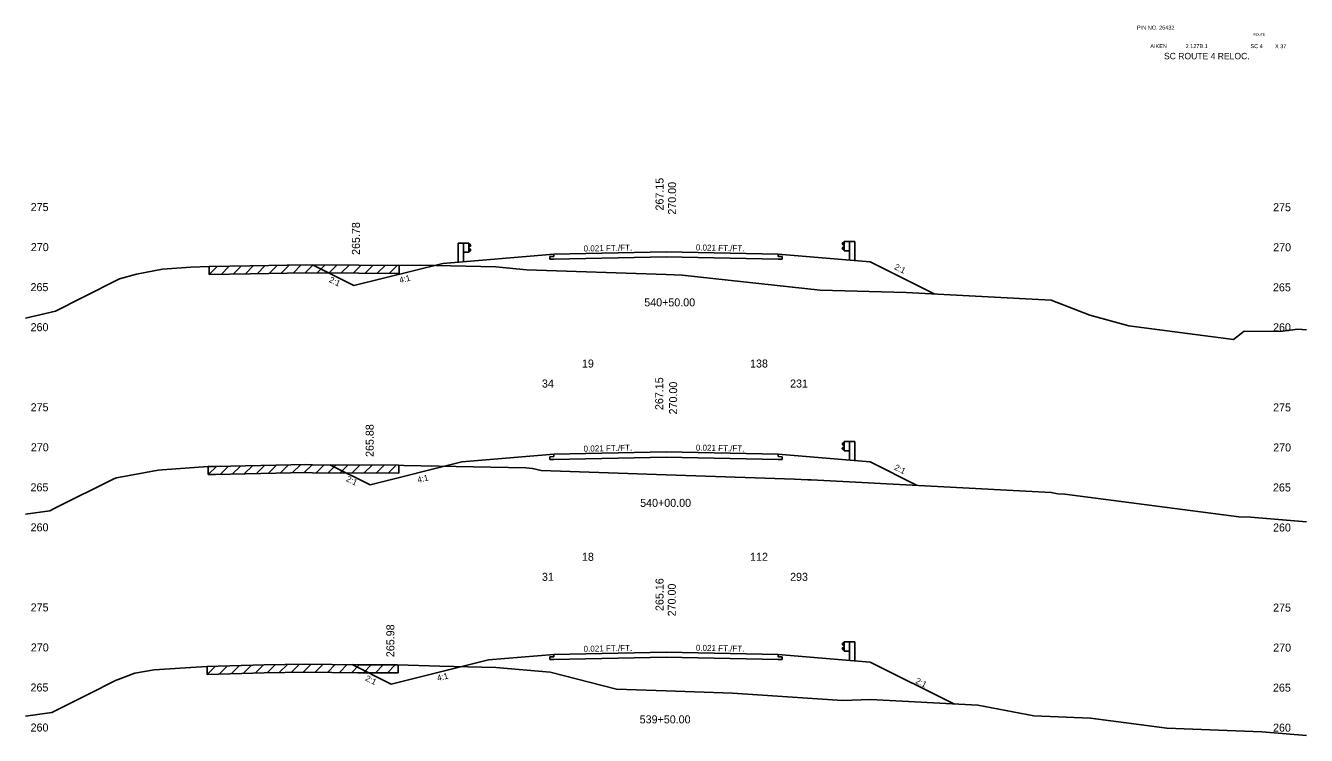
# Model space of a CAD drawing. Extents: x 2967 to 4323, y -3677 to -817.
# Drawn here: x 3555.3 to 3715.3, y -2400.2 to -2311.6 of the extents above; entities that cross this region are included whole.
import ezdxf

# ---------------------------------------------------------------- set-up
doc = ezdxf.new("R2010")
doc.units = 0
for name, color, linetype in [('Level 1', 7, 'Continuous'), ('Level 10', 7, 'Continuous'), ('Level 11', 7, 'Continuous'), ('Level 12', 7, 'Continuous'), ('Level 20', 7, 'Continuous'), ('Level 24', 7, 'Continuous'), ('Level 3', 7, 'Continuous'), ('Level 32', 7, 'Continuous'), ('Level 33', 7, 'Continuous'), ('Level 59', 7, 'Continuous'), ('Level 6', 7, 'Continuous'), ('Level 60', 7, 'Continuous'), ('Level 61', 7, 'Continuous'), ('Level 7', 7, 'Continuous')]:
    doc.layers.add(name, color=color, linetype=linetype)

msp = doc.modelspace()

# ---------------------------------------------------------------- linework, layer by layer
at = {"layer": 'Level 11'}
for p, q in [((3621.35, -2340.43), (3620.85, -2340.44)), ((3620.85, -2340.44), (3620.85, -2340.78)), ((3620.85, -2340.78), (3621.35, -2340.77)), ((3621.35, -2340.13), (3621.35, -2340.43)), ((3649.35, -2340.43), (3649.35, -2340.13)), ((3649.85, -2340.44), (3649.35, -2340.43)), ((3649.35, -2340.77), (3649.85, -2340.78)), ((3649.85, -2340.78), (3649.85, -2340.44)), ((3621.35, -2365.43), (3620.85, -2365.44)), ((3620.85, -2365.44), (3620.85, -2365.78)), ((3620.85, -2365.78), (3621.35, -2365.77)), ((3621.35, -2365.13), (3621.35, -2365.43)), ((3649.35, -2365.43), (3649.35, -2365.13)), ((3649.85, -2365.44), (3649.35, -2365.43)), ((3649.35, -2365.77), (3649.85, -2365.78)), ((3649.85, -2365.78), (3649.85, -2365.44)), ((3621.35, -2390.13), (3621.35, -2390.43)), ((3649.35, -2390.43), (3649.35, -2390.13)), ((3621.35, -2390.43), (3620.85, -2390.44)), ((3620.85, -2390.44), (3620.85, -2390.78)), ((3620.85, -2390.78), (3621.35, -2390.77)), ((3649.85, -2390.44), (3649.35, -2390.43)), ((3649.35, -2390.77), (3649.85, -2390.78)), ((3649.85, -2390.78), (3649.85, -2390.44))]:
    msp.add_line(p, q, dxfattribs=at)
at = {"layer": 'Level 12'}
for p, q in [((3635.35, -2340.48), (3621.35, -2340.77)), ((3649.35, -2340.77), (3635.35, -2340.48)), ((3635.35, -2365.48), (3621.35, -2365.77)), ((3649.35, -2365.77), (3635.35, -2365.48)), ((3635.35, -2390.48), (3621.35, -2390.77)), ((3649.35, -2390.77), (3635.35, -2390.48))]:
    msp.add_line(p, q, dxfattribs=at)
at = {"layer": 'Level 24'}
for p, q in [((3610.03, -2338.75), (3609.37, -2338.75)), ((3609.37, -2338.75), (3609.37, -2341.13)), ((3610.7, -2338.75), (3610.03, -2338.75)), ((3610.03, -2338.75), (3610.03, -2341.08)), ((3610.7, -2339.91), (3610.7, -2338.75)), ((3610.7, -2338.82), (3610.97, -2339.02)), ((3610.97, -2339.07), (3610.7, -2339.27)), ((3610.97, -2339.02), (3610.97, -2339.07)), ((3657.62, -2338.62), (3657.35, -2338.82)), ((3657.35, -2338.82), (3657.35, -2338.87)), ((3657.35, -2338.87), (3657.62, -2339.07)), ((3657.35, -2339.39), (3657.62, -2339.19)), ((3657.62, -2339.72), (3657.62, -2338.55)), ((3657.62, -2338.55), (3658.28, -2338.55)), ((3658.28, -2338.55), (3658.28, -2340.88)), ((3658.28, -2338.55), (3658.95, -2338.55)), ((3658.95, -2338.55), (3658.95, -2340.93)), ((3610.7, -2339.91), (3610.03, -2339.91)), ((3610.97, -2339.59), (3610.7, -2339.39)), ((3610.7, -2339.84), (3610.97, -2339.64)), ((3610.97, -2339.64), (3610.97, -2339.59)), ((3657.35, -2339.44), (3657.35, -2339.39)), ((3657.62, -2339.64), (3657.35, -2339.44)), ((3657.62, -2339.72), (3658.29, -2339.72)), ((3657.62, -2363.62), (3657.35, -2363.82)), ((3657.35, -2363.82), (3657.35, -2363.87)), ((3657.35, -2363.87), (3657.62, -2364.07)), ((3657.35, -2364.39), (3657.62, -2364.19)), ((3657.35, -2364.44), (3657.35, -2364.39)), ((3657.62, -2364.64), (3657.35, -2364.44)), ((3657.62, -2364.72), (3657.62, -2363.55)), ((3657.62, -2363.55), (3658.28, -2363.55)), ((3657.62, -2364.72), (3658.29, -2364.72)), ((3658.28, -2363.55), (3658.28, -2365.88)), ((3658.28, -2363.55), (3658.95, -2363.55)), ((3658.95, -2363.55), (3658.95, -2365.93)), ((3657.62, -2388.62), (3657.35, -2388.82)), ((3657.62, -2389.72), (3657.62, -2388.55)), ((3657.62, -2388.55), (3658.28, -2388.55)), ((3658.28, -2388.55), (3658.28, -2390.88)), ((3658.28, -2388.55), (3658.95, -2388.55)), ((3658.95, -2388.55), (3658.95, -2390.93)), ((3657.35, -2388.82), (3657.35, -2388.87)), ((3657.35, -2388.87), (3657.62, -2389.07)), ((3657.35, -2389.39), (3657.62, -2389.19)), ((3657.35, -2389.44), (3657.35, -2389.39)), ((3657.62, -2389.64), (3657.35, -2389.44)), ((3657.62, -2389.72), (3658.29, -2389.72))]:
    msp.add_line(p, q, dxfattribs=at)
at = {"layer": 'Level 59'}
for p, q in [((3621.35, -2340.13), (3635.35, -2339.84)), ((3635.35, -2339.84), (3649.35, -2340.13)), ((3621.35, -2365.13), (3635.35, -2364.84)), ((3635.35, -2364.84), (3649.35, -2365.13)), ((3621.35, -2390.13), (3635.35, -2389.84)), ((3635.35, -2389.84), (3649.35, -2390.13))]:
    msp.add_line(p, q, dxfattribs=at)
at = {"layer": 'Level 6'}
for p, q in [((3607.46, -2341.29), (3621.35, -2340.13)), ((3649.35, -2340.13), (3657.35, -2340.8)), ((3657.35, -2340.8), (3660.85, -2341.09)), ((3609.85, -2366.09), (3621.35, -2365.13)), ((3649.35, -2365.13), (3660.85, -2366.09)), ((3613.18, -2390.81), (3621.35, -2390.13)), ((3649.35, -2390.13), (3660.85, -2391.09))]:
    msp.add_line(p, q, dxfattribs=at)
at = {"layer": 'Level 60'}
for p, q in [((3569.2, -2342.62), (3572.44, -2342.02)), ((3572.44, -2342.02), (3576, -2341.78)), ((3576, -2341.78), (3578.28, -2341.7)), ((3578.28, -2341.7), (3583.38, -2341.61)), ((3583.38, -2341.61), (3590.37, -2341.47)), ((3590.37, -2341.47), (3596.97, -2341.5)), ((3596.97, -2341.5), (3601.65, -2341.57)), ((3601.65, -2341.57), (3604.7, -2341.52)), ((3604.7, -2341.52), (3614.11, -2341.71)), ((3614.11, -2341.71), (3617.93, -2342.09)), ((3617.93, -2342.09), (3635.35, -2342.69)), ((3562.46, -2345.55), (3567.08, -2343.24)), ((3567.08, -2343.24), (3569.2, -2342.62)), ((3635.35, -2342.69), (3637.37, -2342.76)), ((3637.37, -2342.76), (3654.6, -2344.62)), ((3559.08, -2347.24), (3562.46, -2345.55)), ((3654.6, -2344.62), (3665.33, -2344.94)), ((3665.33, -2344.94), (3683.48, -2345.88)), ((3683.48, -2345.88), (3688.3, -2347.74)), ((3555.35, -2348.12), (3559.08, -2347.24)), ((3688.3, -2347.74), (3693.18, -2349.08)), ((3693.18, -2349.08), (3706.25, -2350.8)), ((3706.25, -2350.8), (3707.58, -2349.74)), ((3707.58, -2349.74), (3712.02, -2349.8)), ((3712.02, -2349.8), (3714.27, -2349.49)), ((3714.27, -2349.49), (3715.35, -2349.58)), ((3566.7, -2368.07), (3571.9, -2367.1)), ((3571.9, -2367.1), (3572.41, -2367.07)), ((3572.41, -2367.07), (3578.15, -2366.68)), ((3578.15, -2366.68), (3579.07, -2366.66)), ((3579.07, -2366.66), (3590.37, -2366.43)), ((3590.37, -2366.43), (3591.18, -2366.44)), ((3591.18, -2366.44), (3601.91, -2366.5)), ((3601.91, -2366.5), (3602.58, -2366.52)), ((3602.58, -2366.52), (3617.84, -2366.81)), ((3617.84, -2366.81), (3618.69, -2366.89)), ((3618.69, -2366.89), (3619.74, -2367.16)), ((3619.74, -2367.16), (3635.35, -2367.69)), ((3635.35, -2367.69), (3651.38, -2368.23)), ((3559.01, -2371.88), (3566.38, -2368.19)), ((3566.38, -2368.19), (3566.7, -2368.07)), ((3651.38, -2368.23), (3653.06, -2368.34)), ((3653.06, -2368.34), (3653.49, -2368.33)), ((3653.49, -2368.33), (3683.45, -2369.89)), ((3683.45, -2369.89), (3684.31, -2370.06)), ((3684.31, -2370.06), (3685.18, -2370.1)), ((3685.18, -2370.1), (3706.91, -2372.95)), ((3555.35, -2372.61), (3558.39, -2372.19)), ((3558.39, -2372.19), (3559.01, -2371.88)), ((3706.91, -2372.95), (3708.36, -2373)), ((3708.36, -2373), (3715.35, -2373.56)), ((3571.41, -2392.04), (3575.32, -2391.8)), ((3575.32, -2391.8), (3577.99, -2391.62)), ((3577.99, -2391.62), (3585.13, -2391.44)), ((3585.13, -2391.44), (3590.35, -2391.33)), ((3590.35, -2391.33), (3596.86, -2391.42)), ((3596.86, -2391.42), (3601.8, -2391.45)), ((3601.8, -2391.45), (3607.1, -2391.61)), ((3607.1, -2391.61), (3614.11, -2391.75)), ((3614.11, -2391.75), (3620.86, -2392.36)), ((3563.14, -2395.13), (3566.59, -2393.4)), ((3566.59, -2393.4), (3569, -2392.49)), ((3569, -2392.49), (3571.41, -2392.04)), ((3620.86, -2392.36), (3629.17, -2394.48)), ((3558.64, -2397.4), (3563.14, -2395.13)), ((3629.17, -2394.48), (3635.35, -2394.69)), ((3635.35, -2394.69), (3643.64, -2394.97)), ((3643.64, -2394.97), (3657.39, -2395.89)), ((3657.39, -2395.89), (3660.91, -2395.78)), ((3660.91, -2395.78), (3674.32, -2396.48)), ((3674.32, -2396.48), (3681.3, -2397.79)), ((3555.35, -2397.85), (3558.64, -2397.4)), ((3681.3, -2397.79), (3688.38, -2398.11)), ((3688.38, -2398.11), (3697.92, -2399.36)), ((3697.92, -2399.36), (3709.78, -2399.8)), ((3709.78, -2399.8), (3715.35, -2400.24))]:
    msp.add_line(p, q, dxfattribs=at)
at = {"layer": 'Level 61'}
for p, q in [((3579.29, -2341.69), (3578.27, -2342.7)), ((3578.27, -2341.7), (3578.27, -2342.7)), ((3580.79, -2341.66), (3579.77, -2342.68)), ((3582.29, -2341.63), (3581.27, -2342.65)), ((3583.79, -2341.6), (3582.77, -2342.62)), ((3585.29, -2341.57), (3584.27, -2342.59)), ((3586.79, -2341.54), (3585.77, -2342.56)), ((3588.29, -2341.51), (3587.27, -2342.53)), ((3589.79, -2341.48), (3588.77, -2342.5)), ((3591.27, -2341.47), (3590.27, -2342.47)), ((3592.76, -2341.48), (3591.77, -2342.47)), ((3594.26, -2341.49), (3593.27, -2342.48)), ((3595.76, -2341.5), (3594.77, -2342.49)), ((3597.26, -2341.51), (3596.27, -2342.5)), ((3598.76, -2341.53), (3597.77, -2342.51)), ((3600.26, -2341.55), (3599.27, -2342.53)), ((3601.76, -2341.56), (3600.77, -2342.55)), ((3602.02, -2342.56), (3602.02, -2341.56)), ((3578.27, -2342.7), (3578.28, -2342.7)), ((3578.28, -2342.7), (3583.38, -2342.61)), ((3583.38, -2342.61), (3590.37, -2342.47)), ((3590.37, -2342.47), (3596.97, -2342.5)), ((3596.97, -2342.5), (3601.65, -2342.57)), ((3601.65, -2342.57), (3602.02, -2342.56)), ((3579.18, -2366.66), (3578.15, -2367.68)), ((3578.15, -2366.68), (3578.15, -2367.68)), ((3578.15, -2367.68), (3579.07, -2367.66)), ((3579.07, -2367.66), (3590.37, -2367.43)), ((3580.68, -2366.63), (3579.65, -2367.65)), ((3582.18, -2366.6), (3581.15, -2367.62)), ((3583.68, -2366.57), (3582.65, -2367.59)), ((3585.18, -2366.53), (3584.15, -2367.56)), ((3586.68, -2366.5), (3585.65, -2367.52)), ((3588.18, -2366.47), (3587.15, -2367.49)), ((3589.68, -2366.44), (3588.65, -2367.46)), ((3591.15, -2366.44), (3590.15, -2367.43)), ((3590.37, -2367.43), (3591.18, -2367.44)), ((3591.18, -2367.44), (3601.91, -2367.5)), ((3592.65, -2366.45), (3591.65, -2367.44)), ((3594.15, -2366.45), (3593.15, -2367.45)), ((3595.65, -2366.46), (3594.65, -2367.46)), ((3597.15, -2366.47), (3596.15, -2367.47)), ((3598.65, -2366.48), (3597.65, -2367.47)), ((3600.15, -2366.49), (3599.15, -2367.48)), ((3601.65, -2366.49), (3600.65, -2367.49)), ((3601.91, -2367.5), (3601.96, -2367.5)), ((3601.96, -2367.5), (3601.96, -2366.5)), ((3579.07, -2391.6), (3578.04, -2392.62)), ((3578.04, -2391.62), (3578.04, -2392.62)), ((3580.57, -2391.56), (3579.54, -2392.58)), ((3582.07, -2391.52), (3581.04, -2392.55)), ((3583.57, -2391.48), (3582.54, -2392.51)), ((3585.07, -2391.44), (3584.04, -2392.47)), ((3586.56, -2391.41), (3585.54, -2392.43)), ((3588.06, -2391.38), (3587.04, -2392.4)), ((3589.56, -2391.35), (3588.54, -2392.37)), ((3591.04, -2391.34), (3590.04, -2392.34)), ((3592.53, -2391.36), (3591.54, -2392.35)), ((3594.03, -2391.38), (3593.04, -2392.37)), ((3595.53, -2391.41), (3594.54, -2392.39)), ((3597.03, -2391.43), (3596.04, -2392.41)), ((3598.53, -2391.43), (3597.54, -2392.43)), ((3600.03, -2391.44), (3599.04, -2392.44)), ((3601.53, -2391.45), (3600.54, -2392.44)), ((3601.9, -2392.45), (3601.9, -2391.45)), ((3578.04, -2392.62), (3585.13, -2392.44)), ((3585.13, -2392.44), (3590.35, -2392.33)), ((3590.35, -2392.33), (3596.86, -2392.42)), ((3596.86, -2392.42), (3601.8, -2392.45)), ((3601.8, -2392.45), (3601.9, -2392.45))]:
    msp.add_line(p, q, dxfattribs=at)
at = {"layer": 'Level 7'}
for p, q in [((3596.36, -2344.07), (3591.17, -2341.47)), ((3607.46, -2341.29), (3596.36, -2344.07)), ((3660.85, -2341.09), (3668.92, -2345.13)), ((3609.85, -2366.09), (3598.38, -2368.96)), ((3660.85, -2366.09), (3666.71, -2369.02)), ((3593.37, -2366.45), (3598.38, -2368.96)), ((3596.13, -2391.41), (3601.01, -2393.86)), ((3613.18, -2390.81), (3601.01, -2393.86)), ((3660.85, -2391.09), (3671.31, -2396.32))]:
    msp.add_line(p, q, dxfattribs=at)

# ---------------------------------------------------------------- texts
at = {"layer": 'Level 1'}
for s, p in [('19', (3624.85, -2354.3)), ('138', (3645.85, -2354.3)), ('34', (3619.85, -2356.8)), ('231', (3650.85, -2356.8)), ('18', (3624.85, -2378.44)), ('112', (3645.85, -2378.44)), ('31', (3619.85, -2380.94)), ('293', (3650.85, -2380.94))]:
    msp.add_text(s, height=1, dxfattribs=at).set_placement(p)
at = {"layer": 'Level 10'}
for s, p in [('267.15', (3635.04, -2334.69)), ('267.15', (3635, -2359.61)), ('265.16', (3635.04, -2384.71))]:
    msp.add_text(s, height=1, rotation=90, dxfattribs=at).set_placement(p)
for s, p in [('540+50.00', (3632.63, -2346.66)), ('540+00.00', (3632.12, -2371.7)), ('539+50.00', (3632.06, -2398.74))]:
    msp.add_text(s, height=1, dxfattribs=at).set_placement(p)
at = {"layer": 'Level 20'}
for s, height, p in [('PIN NO. 26432', 0.5, (3694.19, -2312.1)), ('ROUTE', 0.3, (3708.73, -2312.85)), ('AIKEN', 0.5, (3695.85, -2314.41)), ('SC ROUTE 4 RELOC.', 0.8, (3697.56, -2315.8)), (' 2.127B.1', 0.5, (3700.07, -2314.41)), ('SC 4', 0.5, (3708.36, -2314.41)), ('X 37', 0.5, (3711.43, -2314.42))]:
    msp.add_text(s, height=height, dxfattribs=at).set_placement(p)
at = {"layer": 'Level 3'}
for s, p in [(' 275', (3555.61, -2334.76)), (' 275', (3710.82, -2334.78)), (' 270', (3555.63, -2339.76)), (' 270', (3710.83, -2339.78)), (' 265', (3555.59, -2344.76)), (' 265', (3710.8, -2344.78)), (' 260', (3555.6, -2349.76)), (' 260', (3710.81, -2349.78)), (' 275', (3555.61, -2359.76)), (' 275', (3710.82, -2359.78)), (' 270', (3555.63, -2364.76)), (' 270', (3710.83, -2364.78)), (' 265', (3555.59, -2369.76)), (' 265', (3710.8, -2369.78)), (' 260', (3555.6, -2374.76)), (' 260', (3710.81, -2374.78)), (' 275', (3555.61, -2384.76)), (' 275', (3710.82, -2384.78)), (' 270', (3555.63, -2389.76)), (' 270', (3710.83, -2389.78)), (' 265', (3555.59, -2394.76)), (' 265', (3710.8, -2394.78)), (' 260', (3555.6, -2399.76)), (' 260', (3710.81, -2399.78))]:
    msp.add_text(s, height=1, dxfattribs=at).set_placement(p)
at = {"layer": 'Level 32'}
for s, rotation, p in [('0.021 FT./FT.', 1.1916, (3625.06, -2339.81)), ('0.021 FT./FT.', 358.8084, (3639.07, -2339.67)), ('2:1', 333.435, (3663.8, -2341.97)), ('2:1', 333.435, (3593.18, -2343.58)), ('4:1', 14.0362, (3602.13, -2343.77)), ('0.021 FT./FT.', 1.1916, (3625.06, -2364.81)), ('0.021 FT./FT.', 358.8084, (3639.07, -2364.67)), ('2:1', 333.435, (3595.32, -2368.45)), ('4:1', 14.0362, (3604.38, -2368.72)), ('2:1', 333.435, (3663.8, -2367.02)), ('0.021 FT./FT.', 1.1916, (3625.06, -2389.81)), ('0.021 FT./FT.', 358.8084, (3639.07, -2389.67)), ('2:1', 333.435, (3597.7, -2393.35)), ('4:1', 14.0362, (3606.85, -2393.47)), ('2:1', 333.435, (3666.44, -2393.68))]:
    msp.add_text(s, height=0.75, rotation=rotation, dxfattribs=at).set_placement(p)
at = {"layer": 'Level 33'}
for s, p in [('265.78', (3597.11, -2340.24)), ('265.88', (3598.83, -2365.47)), ('265.98', (3601.41, -2390.47))]:
    msp.add_text(s, height=1, rotation=90, dxfattribs=at).set_placement(p)
at = {"layer": 'Level 59'}
for p in [(3636.61, -2335.58), (3636.74, -2360.53), (3636.57, -2385.75)]:
    msp.add_text(' 270.00', height=1, rotation=90, dxfattribs=at).set_placement(p)

doc.saveas('drawing.dxf')
